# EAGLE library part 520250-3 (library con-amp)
AMP connector
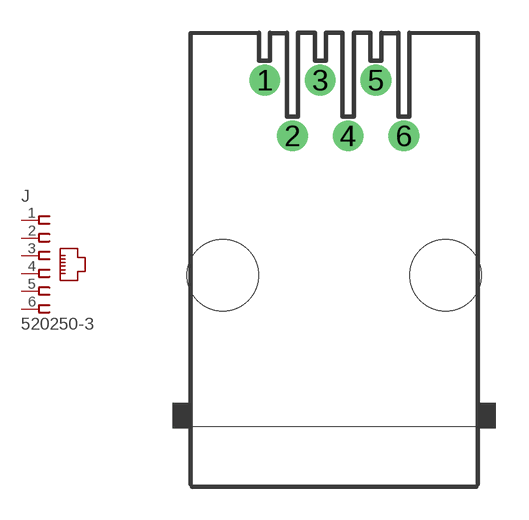
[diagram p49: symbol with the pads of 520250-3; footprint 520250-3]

Designator prefix J

## 520250-3 (MF: TYCO ELECTRONICS; MPN: 5520250-3; OC_FARNELL: unknown; OC_NEWARK: 42K8724)  [520250-3]
1  1  pas
2  2  pas
3  3  pas
4  4  pas
5  5  pas
6  6  pas

## Footprint 520250-3 (pad centres in mm)
Modular Jack with Panel Stops
drill 0.889 round: 1 -3.175,8.89; 2 -1.905,6.35; 3 -0.635,8.89; 4 0.635,6.35; 5 1.905,8.89; 6 3.175,6.35
hole 3.251 at -5.08,0
hole 3.251 at 5.08,0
